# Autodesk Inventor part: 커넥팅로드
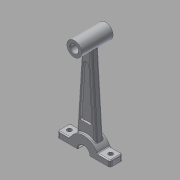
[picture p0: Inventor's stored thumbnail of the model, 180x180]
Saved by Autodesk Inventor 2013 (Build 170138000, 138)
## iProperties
Created: 2016-11
Part Number: 커넥팅로드
Material: 알루미늄 6061
Document SubType Name: Modeling
Designer: mduedu
Density: 2.71 g/cm^3
Mass: 62.0571 g
Surface Area: 108.143 cm^2
Volume: 22.8993 cm^3
Author: mduedu
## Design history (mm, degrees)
sketch "스케치1" dims "d0" = 30, "d3" = 15
  geometry: L1 (0, 0)-(0, 96); L2 (-5, 90.41)-(-10, 11.18); L3 (5, 90.41)-(10, 11.18); C1 r 6 at (0, 0); C2 r 4 at (0, 96); 3 further points
  constraints: 6 end point, 4 coincident, 2 centre point, 2 symmetric about line, 1 vertical, 6 other
  dimensions: "d1" = 12 diameter of C1; "d2" = 8 diameter of C2; "d4" = 96 distance of L1.start L1.end; "d6" = 10 distance from line of L1 L2.end; "d7" = 5 distance from line of L1 L2.start
extrude "돌출1" new body sketch "스케치1" stored distance "d8" = 13; taper "d9" = 0 deg
extrude "돌출2" join sketch "스케치1" stored distance "d10" = 32; taper "d11" = 0 deg
sketch "스케치2"
  geometry: L1 (5, 90.41)-(10, 11.18) reference; L2 (-5, 90.41)-(-10, 11.18) reference; A1 r 7.5 centre (0, 96) between (5, 90.41) and (-5, 90.41) reference; A2 r 15 centre (0, 0) between (10, 11.18) and (-10, 11.18) reference
extrude "돌출3" join sketch "스케치2" stored distance "d12" = 8; taper "d13" = 0 deg
sketch "스케치3"
  geometry: L1 (-2.732, 78.715)-(-6.171, 24.226); L2 (2.732, 78.715)-(6.171, 24.226); L3 (0, 78.5)-(0, 25); A1 r 17.5 centre (0, 96) between (-2.732, 78.715) and (2.732, 78.715); A2 r 25 centre (0, 0) between (6.171, 24.226) and (-6.171, 24.226); 9 further points; 2 other entities
  constraints: 6 end point, 6 point on circle, 2 centre point, 1 symmetric about line, 1 vertical alignment, 6 other
  dimensions: "d18" = 10 dimension on A1; "d19" = 10 dimension on A2; "d20" = 3 dimension on L1
extrude "돌출4" cut sketch "스케치3" distance "d21" = 2; taper "d22" = 0 deg
fillet "모깎기1" dims "d23" = 2
fillet "모깎기2" dims "d24" = 2
fillet "모깎기3" dims "d25" = 1
chamfer "모따기1" distance "d26" = 0.5; stored, may be unused: second distance "d27" = 2, angle "d28" = 45 deg
sketch "스케치4"
  geometry: L1 (-27, -6)-(-13.748, -6); L2 (27, -6)-(27, 6); L3 (27, 6)-(13.748, 6); L4 (-27, 6)-(-27, -6); L5 (-27, -6)-(27, 6); L6 (27, -6)-(-27, 6); L7 (-13.748, 6)-(-27, 6); L8 (13.748, 6)-(-13.748, 6); L9 (13.748, -6)-(27, -6); L10 (-13.748, -6)-(13.748, -6); A1 r 15 centre (0, 0) between (-13.748, 6) and (13.748, 6) reference; 1 further point
  constraints: 20 end point, 10 parallel, 4 point on circle, 3 horizontal, 3 perpendicular, 2 midpoint
  dimensions: "d29" = 54 distance of L1.start L2.start; "d31" = 12 distance of L2.start L2.end
extrude "돌출5" join sketch "스케치4" stored distance "d32" = 0; taper "d33" = 0 deg
fillet "모깎기4" dims "d34" = 2
fillet "모깎기5" dims "d35" = 1
fillet "모깎기6" dims "d36" = 1
sketch "스케치5"
  geometry: L1 (1, 0)-(1, 9) reference; L2 (-18.5, 20.5)-(-33.5, 20.5) reference; L3 (-33.5, -11.5)-(-18.5, -11.5) reference; L4 (-26, 20.5)-(-26, -11.5); 3 further points
  constraints: 2 end point, 2 midpoint, 1 horizontal alignment, 1 symmetric about line
  dimensions: "d37" = 6 distance from line of point (-5, 4.5) L1
feature "분할1"
sketch "스케치7"
  geometry: 2 further points
  constraints: 2 other
hole "구멍2" sketch "스케치7" at (-47, 4.5), (-5, 4.5) diameter "d45" = 4.5; stored, may be unused: countersink angle "d49" = 90 deg, drill point angle "d51" = 0 deg; dims "d46" = 6, "d47" = 4, "d48" = 2, "d50" = 8
node "솔리드1"
mirror "대칭1"
other parameters: "d16" = 4, "d17" = 4
